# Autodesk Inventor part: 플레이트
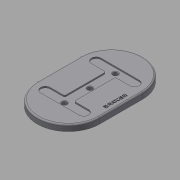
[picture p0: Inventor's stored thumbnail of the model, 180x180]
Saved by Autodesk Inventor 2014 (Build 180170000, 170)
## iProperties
Created: 2016-08
Part Number: 플레이트
Material: Aluminum 6061
Document SubType Name: Modeling
Designer: mduedu
Density: 2.71 g/cm^3
Appearance: Default
Mass: 825.154 g
Surface Area: 591.117 cm^2
Volume: 304.485 cm^3
Author: mduedu
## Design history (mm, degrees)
sketch "스케치1" dims "d0" = 220, "d2" = 130
  geometry: L1 (45, 65)-(-45, 65); L2 (-45, 65)-(-45, -65); L3 (-45, -65)-(45, -65); L4 (45, -65)-(45, 65); L5 (45, 65)-(-45, -65); L6 (-45, 65)-(45, -65); 5 further points
  constraints: 12 end point, 5 midpoint, 2 parallel, 2 vertical alignment, 1 coincident, 1 horizontal, 1 perpendicular, 4 other
extrude "돌출1" new body sketch "스케치1" distance "d3" = 13; taper "d4" = 0 deg
sketch "스케치2"
  geometry: L1 (-63, -50)-(63, -50); L2 (63, -50)-(63, 50); L3 (63, 50)-(-63, 50); L4 (-63, 50)-(-63, -50); L5 (-63, -50)-(63, 50); L6 (63, -50)-(-63, 50); L7 (-63, 50)-(-43, 50); L8 (-43, 50)-(-43, -50); L9 (-43, -50)-(-63, -50); L10 (-63, -50)-(-63, 50); L11 (63, 50)-(43, 50); L12 (43, 50)-(43, -50); L13 (43, -50)-(63, -50); L14 (63, -50)-(63, 50); L15 (-43, -10)-(43, -10); L16 (43, -10)-(43, 10); L17 (43, 10)-(-43, 10); L18 (-43, 10)-(-43, -10); L19 (-43, -10)-(43, 10); L20 (43, -10)-(-43, 10); 1 further point
  constraints: 40 end point, 8 parallel, 4 horizontal, 4 midpoint, 4 perpendicular, 3 point on line
  dimensions: "d18" = 126 distance of L3.end L2.end; "d19" = 100 distance of L2.end L1.end; "d20" = 20 distance of L8.end L9.end; "d21" = 20 distance of L12.end L13.end (= d20); "d22" = 20 distance of L15.end L16.end
extrude "돌출3" cut sketch "스케치2" distance "d23" = 3; taper "d24" = 0 deg
fillet "모깎기2"
fillet "모깎기3"
fillet "모깎기4"
fillet "모깎기5"
fillet "모깎기6" dims "d25" = 3
sketch "스케치4"
  geometry: L1 (-43, -40)-(-43, -13) reference; L2 (-40, -10)-(40, -10) reference; L3 (43, -13)-(43, -40) reference; L4 (63, -40)-(63, 40) reference; L5 (43, 40)-(43, 13) reference; L6 (40, 10)-(-40, 10) reference; L7 (-43, 13)-(-43, 40) reference; L8 (-63, 40)-(-63, -40) reference; L9 (45, -65)-(-45, -65) reference; L10 (-45, 65)-(45, 65) reference; L11 (-53, 40)-(-53, -40); L12 (53, 40)-(53, -40); L13 (-53, 0)-(53, 0); C1 r 5 at (-53, 0); C2 r 5 at (0, 0); C3 r 5 at (53, 0); A1 r 10 centre (-53, -40) between (-63, -40) and (-43, -40) reference; A2 r 3 centre (-40, -13) between (-40, -10) and (-43, -13) reference; A3 r 3 centre (40, -13) between (43, -13) and (40, -10) reference; A4 r 10 centre (53, -40) between (43, -40) and (63, -40) reference; A5 r 10 centre (53, 40) between (63, 40) and (43, 40) reference; A6 r 3 centre (40, 13) between (40, 10) and (43, 13) reference; A7 r 3 centre (-40, 13) between (-43, 13) and (-40, 10) reference; A8 r 10 centre (-53, 40) between (-43, 40) and (-63, 40) reference; A9 r 65 centre (45, 0) between (45, -65) and (45, 65) reference; A10 r 65 centre (-45, 0) between (-45, 65) and (-45, -65) reference; 1 further point
  constraints: 6 end point, 3 centre point, 3 coincident, 2 midpoint, 1 parallel, 1 perpendicular
  dimensions: "d26" = 10 diameter of C1; "d27" = 10 diameter of C2; "d28" = 10 diameter of C3
extrude "돌출4" cut sketch "스케치4" stored distance "d29" = 3; taper "d30" = 0 deg
chamfer "모따기2" distance "d31" = 1; stored, may be unused: second distance "d32" = 2, angle "d33" = 45 deg
fillet "모깎기1" dims "d14" = 3
sketch "스케치3"
  geometry: L1 (-45, -65)-(45, -65) reference; 2 further points
  constraints: 1 vertical alignment, 1 other
  dimensions: "d15" = 12 distance from line of point (0, -53) L1
feature "엠보싱1" sketch "스케치3" dims "d0" = 220, "d2" = 130, "d16" = 0.5, "d17" = 0
node "솔리드1"
node "절단 모서리 투영1"
